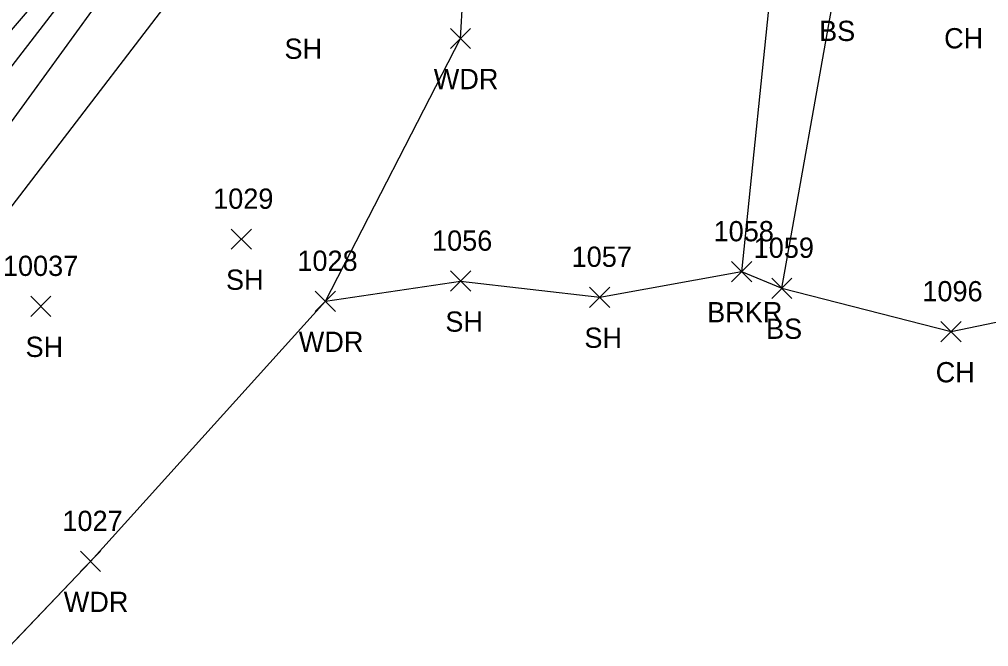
# Model space of a CAD drawing. Extents: x 1651685 to 1653558, y 889533 to 891085.
# Drawn here: x 1652635.2 to 1652731, y 890075.4 to 890137.3 of the extents above; entities that cross this region are included whole.
import ezdxf

# ---------------------------------------------------------------- set-up
doc = ezdxf.new("R2010")
doc.units = 0
for name, color, linetype in [('L_A', 7, 'Continuous'), ('L_I', 7, 'Continuous'), ('L_TIC', 7, 'Continuous'), ('LAWA', 7, 'Continuous'), ('LAWE', 7, 'Continuous'), ('LELB', 7, 'Continuous'), ('LSOGP', 7, 'Continuous')]:
    doc.layers.add(name, color=color, linetype=linetype)

msp = doc.modelspace()

# ---------------------------------------------------------------- linework, layer by layer
at = {"layer": 'L_TIC'}
for points in [[(1652677.783, 890134.452), (1652679.783, 890136.452)], [(1652679.783, 890134.452), (1652677.783, 890136.452)], [(1652656.136, 890114.641), (1652658.136, 890116.641)], [(1652658.136, 890114.641), (1652656.136, 890116.641)], [(1652705.559, 890111.43), (1652707.559, 890113.43)], [(1652707.559, 890111.43), (1652705.559, 890113.43)], [(1652677.803, 890110.501), (1652679.803, 890112.501)], [(1652679.803, 890110.501), (1652677.803, 890112.501)], [(1652709.525, 890109.796), (1652711.525, 890111.796)], [(1652711.525, 890109.796), (1652709.525, 890111.796)], [(1652691.535, 890108.907), (1652693.535, 890110.907)], [(1652693.535, 890108.907), (1652691.535, 890110.907)], [(1652636.339, 890108.008), (1652638.339, 890110.008)], [(1652638.339, 890108.008), (1652636.339, 890110.008)], [(1652664.447, 890108.508), (1652666.447, 890110.508)], [(1652666.447, 890108.508), (1652664.447, 890110.508)], [(1652726.234, 890105.503), (1652728.234, 890107.503)], [(1652728.234, 890105.503), (1652726.234, 890107.503)], [(1652641.237, 890082.822), (1652643.237, 890084.822)], [(1652643.237, 890082.822), (1652641.237, 890084.822)]]:
    msp.add_lwpolyline(points, dxfattribs=at)
at = {"layer": 'LAWA'}
msp.add_lwpolyline([(1652552.288, 889965.957), (1652571.673, 889995.454), (1652586.672, 890018.83), (1652616.646, 890057.034), (1652642.237, 890083.822), (1652665.447, 890109.508), (1652678.783, 890135.452), (1652680.403, 890163.124)], dxfattribs=at)
at = {"layer": 'LAWE'}
msp.add_lwpolyline([(1652706.559, 890112.43), (1652709.687, 890142.851), (1652715.024, 890160.357), (1652716.197, 890160.404), (1652710.632, 890173.639), (1652706.265, 890184.27), (1652703.203, 890199.74), (1652702.705, 890206.049)], dxfattribs=at)
at = {"layer": 'LELB'}
for points in [[(1652059.958, 889769.148), (1652077.097, 889776.338), (1652118.687, 889793.555), (1652148.832, 889805.136), (1652195.565, 889824.702), (1652235.22, 889839.021), (1652273.168, 889851.707), (1652312.186, 889868.505), (1652346.463, 889887.35), (1652384.438, 889904.888), (1652418.627, 889927.641), (1652449.257, 889948.785), (1652484.179, 889973.177), (1652505.899, 889994.659), (1652536.895, 890025.511), (1652566.282, 890055.689), (1652594.629, 890083.579), (1652622.175, 890122.044), (1652650.057, 890154.468), (1652669.869, 890181.835), (1652676.091, 890189.411), (1652687.771, 890202.227), (1652700.091, 890224.174)], [(1652510.075, 889988.608), (1652541.256, 890021.657), (1652570.449, 890051.196), (1652599.255, 890080.662), (1652627.515, 890117.732), (1652652.742, 890152.479), (1652673.773, 890178.689), (1652683.325, 890184.776), (1652690.804, 890198.36), (1652694.159, 890203.394)], [(1652425.64, 889918.847), (1652456.726, 889936.262), (1652476.981, 889952.39), (1652484.779, 889967.501), (1652507.93, 889991.53), (1652539.732, 890022.766), (1652568.751, 890053.154), (1652596.439, 890082.379), (1652624.715, 890120.116), (1652650.778, 890153.905), (1652671.989, 890180.33), (1652678.44, 890186.862), (1652688.877, 890200.577)], [(1652511.691, 889985.78), (1652544.244, 890018.707), (1652572.567, 890047.754), (1652604.473, 890076.616), (1652630.903, 890114.293), (1652657.793, 890149.33), (1652679.001, 890174.399)], [(1652710.525, 890110.796), (1652715.766, 890140.208), (1652724.235, 890157.573), (1652719.518, 890168.815)]]:
    msp.add_lwpolyline(points, dxfattribs=at)
at = {"layer": 'LSOGP'}
msp.add_lwpolyline([(1652616.645, 890057.032), (1652642.236, 890083.818), (1652665.447, 890109.509), (1652678.803, 890111.499), (1652692.534, 890109.909), (1652706.557, 890112.433), (1652710.524, 890110.797), (1652727.235, 890106.507), (1652734.22, 890107.968), (1652741.293, 890109.75), (1652746.222, 890111.78), (1652751.398, 890109.933), (1652761.813, 890104.34), (1652771.714, 890103.934), (1652773.138, 890124.336), (1652772.318, 890136.58), (1652777.868, 890152.665), (1652789.757, 890178.291), (1652783.992, 890192.515), (1652776.245, 890205.046), (1652781.971, 890232.174)], dxfattribs=at)

# ---------------------------------------------------------------- texts
at = {"layer": 'L_A'}
for s, p in [('BS', (1652714.207, 890135.208)), ('CH', (1652726.555, 890134.481)), ('SH', (1652661.398, 890133.448)), ('WDR', (1652676.145, 890130.452)), ('SH', (1652655.624, 890110.641)), ('BRKR', (1652703.15, 890107.43)), ('SH', (1652677.291, 890106.501)), ('BS', (1652708.966, 890105.796)), ('SH', (1652691.023, 890104.907)), ('SH', (1652635.827, 890104.008)), ('WDR', (1652662.809, 890104.508)), ('CH', (1652725.722, 890101.503)), ('WDR', (1652639.599, 890078.822))]:
    msp.add_text(s, height=2, dxfattribs=at).set_placement(p)
at = {"layer": 'L_I'}
for s, p in [('1029', (1652654.357, 890118.641)), ('1058', (1652703.788, 890115.43)), ('1056', (1652675.976, 890114.501)), ('1059', (1652707.746, 890113.796)), ('1028', (1652662.675, 890112.508)), ('1057', (1652689.764, 890112.907)), ('10037', (1652633.591, 890112.008)), ('1096', (1652724.407, 890109.503)), ('1027', (1652639.466, 890086.822))]:
    msp.add_text(s, height=2, dxfattribs=at).set_placement(p)

doc.saveas('drawing.dxf')
